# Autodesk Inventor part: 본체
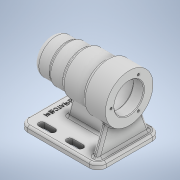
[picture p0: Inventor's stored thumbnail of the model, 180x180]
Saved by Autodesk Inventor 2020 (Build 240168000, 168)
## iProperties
Created: 2021-10
Part Number: 본체
Material: 일반
Document SubType Name: Modeling
Designer: user
Density: 1 g/cm^3
Appearance: 기본값
Author: user
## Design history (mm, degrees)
sketch "스케치1"
  geometry: L1 (0, 0)-(112, 0); L2 (0, 0)-(0, 25); L3 (0, 25)-(24, 25); L4 (24, 25)-(24, 27); L5 (24, 27)-(46, 27); L6 (46, 27)-(46, 30); L7 (46, 30)-(80, 30); L8 (80, 30)-(80, 34); L9 (80, 34)-(112, 34); L10 (112, 34)-(112, 0)
  constraints: 20 end point, 8 perpendicular, 1 horizontal, 1 vertical
  dimensions: "d0" = 112 distance of L1.start L1.end; "d1" = 50 diameter of L3 L1; "d2" = 54 diameter of L5 L1; "d3" = 60 diameter of L7 L1; "d4" = 68 diameter of L9 L1; "d5" = 24 distance from line of L2 L4.end; "d6" = 46 distance from line of L2 L6.end; "d7" = 80 distance from line of L2 L8.end
revolve "회전1" sketch "스케치1" stored, may be unused: angle "d8" = 90 deg
sketch "스케치2"
  geometry: 1 further point
hole "구멍1" sketch "스케치2" at (0, 0) diameter "d9" = 42; stored, may be unused: countersink angle "d13" = 90 deg, drill point angle "d15" = 0 deg; dims "d10" = 8, "d11" = 4, "d12" = 2, "d14" = 15
sketch "스케치3"
  geometry: 1 further point
hole "구멍2" sketch "스케치3" at (0, 0) diameter "d16" = 48; stored, may be unused: countersink angle "d20" = 90 deg, drill point angle "d22" = 0 deg; dims "d17" = 8, "d18" = 4, "d19" = 2, "d21" = 54
sketch "스케치4"
  geometry: 1 further point
hole "구멍3" sketch "스케치4" at (0, 0) diameter "d23" = 42; stored, may be unused: countersink angle "d27" = 90 deg, drill point angle "d29" = 0 deg; dims "d24" = 8, "d25" = 4, "d26" = 2, "d28" = 12
sketch "스케치5"
  geometry: 1 further point
hole "구멍4" sketch "스케치5" at (0, 0) diameter "d30" = 35; stored, may be unused: countersink angle "d34" = 90 deg, drill point angle "d36" = 0 deg; dims "d31" = 8, "d32" = 4, "d33" = 2, "d35" = 18
sketch "스케치6"
  geometry: 1 further point
hole "구멍5" sketch "스케치6" at (0, 0) diameter "d37" = 32; stored, may be unused: countersink angle "d41" = 90 deg, drill point angle "d43" = 0 deg; dims "d38" = 8, "d39" = 4, "d40" = 2, "d42" = 4
sketch "스케치7"
  geometry: 1 further point
hole "구멍6" sketch "스케치7" at (0, 0) diameter "d44" = 21; stored, may be unused: countersink angle "d48" = 90 deg, drill point angle "d50" = 0 deg; dims "d45" = 8, "d46" = 4, "d47" = 2, "d49" = 3
node "작업 평면1"
sketch "스케치8"
  geometry: L1 (0, -45)-(-112, -45); L2 (-112, -45)-(-112, 45); L3 (-112, 45)-(0, 45); L4 (0, 45)-(0, -45); L5 (0, -45)-(-112, 45); L6 (-112, -45)-(0, 45); 3 further points
  constraints: 12 end point, 3 midpoint, 2 parallel, 1 coincident, 1 horizontal, 1 perpendicular
  dimensions: "d52" = 112 distance of L1.start L1.end; "d53" = 90 distance of L1.end L2.end
extrude "돌출1" join sketch "스케치8" distance "d54" = 8; taper "d55" = 0 deg
node "작업 평면2"
sketch "스케치9"
  geometry: L1 (-24.658, 23.409)-(-62, 37); L2 (-70, 45)-(-62, 45) reference; L3 (-62, -45)-(-62, 45) reference; 2 further points
  constraints: 2 end point, 1 point on line, 2 other
  dimensions: "d57" = 8 distance from line of L2 L1.end; "d58" = 110 deg angle of L3 L1
feature "리브1" sketch "스케치9" dims "d59" = 40, "d60" = 8, "d61" = 0, "d62" = 0, "d63" = 1, "d64" = 1
sketch "스케치10"
  geometry: L1 (36.378, -27)-(27, -62); L2 (0, -70)-(0, -62) reference; L3 (112, -62)-(0, -62) reference; L4 (24, -27)-(46, -27) reference; 1 further point
  constraints: 2 end point, 2 point on line
  dimensions: "d65" = 27 distance from line of L2 L1.end; "d66" = 105 deg angle of L3 L1
feature "리브2" sketch "스케치10" dims "d67" = 30, "d68" = 8, "d69" = 0, "d70" = 0, "d71" = 1, "d72" = 1
fillet "모깎기1" dims "d73" = 12
sketch "스케치11"
  geometry: L1 (20, -33)-(35, -33); L2 (20, -37.5)-(35, -37.5); L3 (35, -28.5)-(20, -28.5); L4 (60, -33)-(75, -33); L5 (60, -28.5)-(75, -28.5); L6 (75, -37.5)-(60, -37.5); L7 (0, 33)-(0, -33) reference; A1 r 4.5 centre (20, -33) between (20, -28.5) and (20, -37.5); A2 r 4.5 centre (35, -33) between (35, -37.5) and (35, -28.5); A3 r 4.5 centre (60, -33) between (60, -28.5) and (60, -37.5); A4 r 4.5 centre (75, -33) between (75, -37.5) and (75, -28.5); 3 further points
  constraints: 16 end point, 8 point on circle, 8 tangent, 4 centre point, 2 horizontal, 2 midpoint, 2 parallel
  dimensions: "d74" = 15 distance of L1.end L1.start; "d75" = 15 distance of L4.end L4.start; "d76" = 9 distance between parallel lines of L2 L3; "d77" = 9 distance between parallel lines of L6 L5; "d78" = 20 distance from line of L7 L1.start; "d79" = 25 distance of L4.start L1.end; "d80" = 33 vertical distance of L1.start point (0, 0); "d81" = 33 vertical distance of point (0, 0) L4.start
extrude "돌출2" cut sketch "스케치11" extent not by distance; stored distance "d82" = 0; taper "d83" = 0 deg
sketch "스케치12"
  geometry: 2 further points
  constraints: 1 horizontal alignment
  dimensions: "d84" = 26 distance of point (-26, 0) point (0, 0)
hole "구멍7" sketch "스케치12" at (-26, 0) diameter "d85" = 3.242; stored, may be unused: countersink angle "d89" = 90 deg, drill point angle "d91" = 118 deg; dims "d86" = 8, "d87" = 4, "d88" = 2, "d90" = 11
fillet "모깎기2" dims "d95" = 8
fillet "모깎기3" dims "d96" = 3
fillet "모깎기4" dims "d97" = 3
fillet "모깎기5" dims "d98" = 0.3
fillet "모깎기6" dims "d99" = 3
chamfer "모따기1" distance "d100" = 1; stored, may be unused: second distance "d101" = 2, angle "d102" = 45 deg
fillet "모깎기7" dims "d103" = 3
fillet "모깎기8" dims "d104" = 3
fillet "모깎기9" dims "d105" = 3
fillet "모깎기10" dims "d106" = 3
sketch "스케치13"
  geometry: L1 (0, 33)-(0, -33) reference; A1 r 4.5 centre (20, 33) between (20, 37.5) and (20, 28.5) reference; 2 further points
  constraints: 1 other
  dimensions: "d107" = 12 distance from line of L1 point (12, 0); "d108" = 33 vertical distance of point (12, 0) A1.centre
feature "엠보싱1" sketch "스케치13" dims "d19" = 2, "d109" = 0.5, "d110" = 0
node "솔리드1"
mirror "미러1"
mirror "미러2"
pattern_circular "원형 패턴1" dims angle "d93" = 360 deg
feature "A9D066F2-1C7D-4E18-AEED-F7BC21143FA4" dims "d9" = 42, "d10" = 8, "d11" = 4, "d12" = 2, "d13" = 90 deg, "d14" = 15, "d15" = 0
other parameters: "d56" = 104
